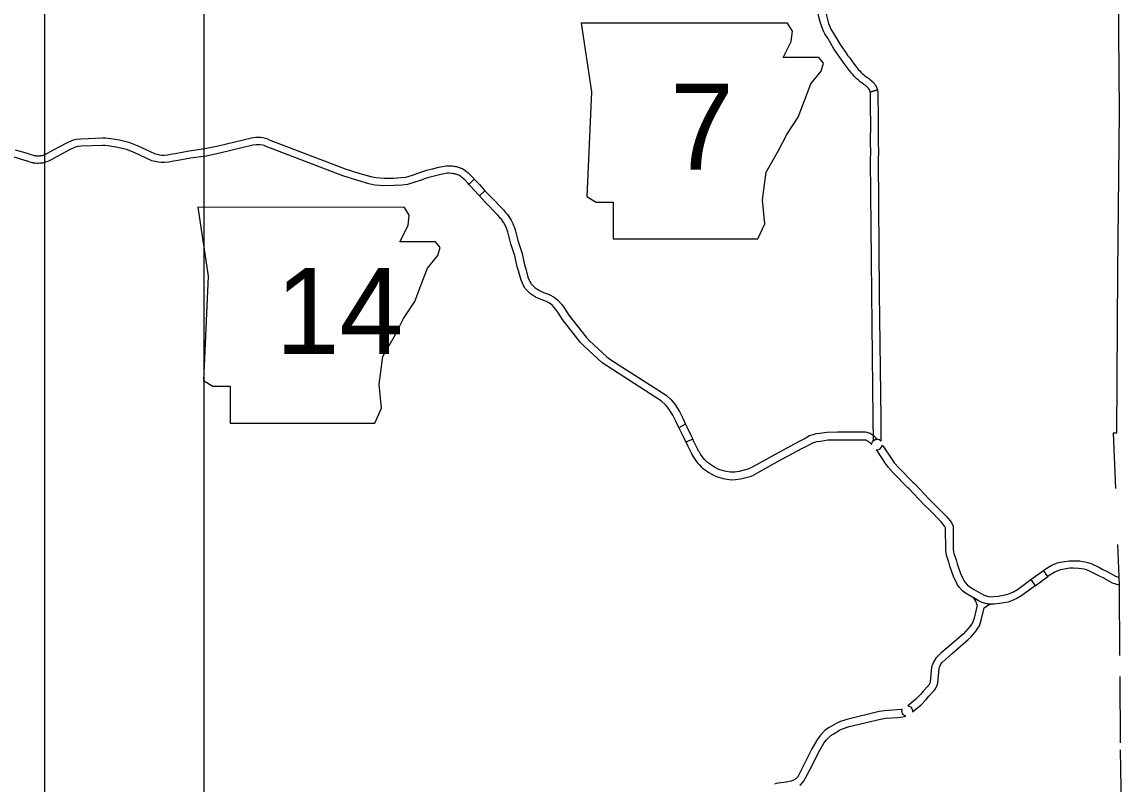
# Model space of a CAD drawing. Extents: x 77230 to 630905, y 790554 to 1662844.
# Drawn here: x 585543 to 621976, y 1603582 to 1628851 of the extents above; entities that cross this region are included whole.
import ezdxf

# ---------------------------------------------------------------- set-up
doc = ezdxf.new("R2010")
doc.units = 0
for name, color, linetype in [('Level 10', 7, 'Continuous'), ('Level 24', 7, 'Continuous'), ('Level 28', 7, 'Continuous'), ('Level 43', 7, 'Continuous')]:
    doc.layers.add(name, color=color, linetype=linetype)

msp = doc.modelspace()

# ---------------------------------------------------------------- linework, layer by layer
at = {"layer": 'Level 10'}
msp.add_line((613598, 1615232), (613558, 1615243), dxfattribs=at)
for points in [[(612461, 1627963), (612252, 1628310), (612161, 1628461), (612128, 1628523), (612090, 1628600), (612047, 1628721), (612001, 1628861), (611963, 1629018), (611939, 1629147), (611842, 1629677), (611783, 1629956), (611720, 1630342), (611665, 1630570), (611633, 1630696), (611560, 1630975), (611541, 1631046), (611530, 1631097), (611518, 1631152), (611504, 1631237)], [(611753, 1631262), (611764, 1631199), (611775, 1631148), (611784, 1631104), (611801, 1631040), (611875, 1630759), (611908, 1630630), (611965, 1630391), (612029, 1630003), (612088, 1629725), (612185, 1629192), (612208, 1629070), (612242, 1628929), (612283, 1628802), (612321, 1628697), (612350, 1628637), (612378, 1628585), (612466, 1628439), (612668, 1628104)], [(613903, 1626598), (613663, 1626529), (613657, 1626551), (613653, 1626564), (613650, 1626571), (613648, 1626577), (613644, 1626585), (613641, 1626593), (613637, 1626601), (613633, 1626608), (613631, 1626612), (613627, 1626619), (613625, 1626622), (613621, 1626628), (613615, 1626636), (613612, 1626642), (613606, 1626648), (613601, 1626654), (613584, 1626673), (613572, 1626685), (613562, 1626696), (613533, 1626721), (613511, 1626739), (613489, 1626757), (613454, 1626782), (613391, 1626827), (613333, 1626872), (613274, 1626919), (613231, 1626957), (613190, 1626995), (613130, 1627056), (613080, 1627111), (613043, 1627154), (612970, 1627246), (612929, 1627303), (612768, 1627521), (612719, 1627589), (612610, 1627745), (612461, 1627963)], [(612668, 1628104), (612815, 1627887), (612923, 1627734), (612970, 1627668), (613131, 1627450), (613169, 1627397), (613235, 1627314), (613267, 1627277), (613312, 1627228), (613365, 1627174), (613398, 1627143), (613435, 1627111), (613488, 1627068), (613539, 1627028), (613600, 1626985), (613640, 1626956), (613668, 1626934), (613696, 1626911), (613733, 1626878), (613752, 1626860), (613767, 1626843), (613789, 1626819), (613798, 1626808), (613809, 1626795), (613819, 1626781), (613827, 1626770), (613835, 1626759), (613842, 1626746), (613849, 1626735), (613855, 1626723), (613861, 1626712), (613867, 1626700), (613873, 1626686), (613879, 1626672), (613885, 1626657), (613890, 1626642), (613896, 1626623), (613903, 1626598)], [(613713, 1619856), (613676, 1624278), (613683, 1624550), (613673, 1624835), (613678, 1625531), (613675, 1625946), (613667, 1626209), (613666, 1626484), (613663, 1626529), (613903, 1626598)], [(613903, 1626598), (613916, 1626499), (613917, 1626213), (613925, 1625951), (613928, 1625531), (613923, 1624839), (613933, 1624551), (613926, 1624276), (613963, 1619859)], [(587003, 1624832), (587214, 1624932), (587291, 1624956), (587348, 1624970), (587489, 1624978), (588217, 1625009)], [(588217, 1625009), (588312, 1625005), (588485, 1624985), (588771, 1624938), (589084, 1624867), (589362, 1624758), (589934, 1624487), (590115, 1624445), (590168, 1624440), (590261, 1624439), (590371, 1624450), (590527, 1624480), (590621, 1624492), (591087, 1624581), (591606, 1624654), (592045, 1624742), (593148, 1625012), (593295, 1625034), (593458, 1625028), (593573, 1625009), (593662, 1624987), (593739, 1624946), (596262, 1623982), (596746, 1623830), (597105, 1623726), (597275, 1623692), (597417, 1623679), (597548, 1623671), (597875, 1623674), (598115, 1623691), (598267, 1623710)], [(587122, 1624612), (586712, 1624390), (586506, 1624280), (586424, 1624241), (586364, 1624213), (586328, 1624199), (586290, 1624187), (586254, 1624178), (586218, 1624172), (586184, 1624168), (586131, 1624165), (586079, 1624164), (586044, 1624164), (585996, 1624167), (585972, 1624169), (585951, 1624171), (585927, 1624174), (585901, 1624180), (585876, 1624185), (585851, 1624192), (585765, 1624219), (585693, 1624243), (585642, 1624259), (585247, 1624377)], [(585319, 1624617), (585715, 1624498), (585770, 1624480), (585842, 1624457), (585922, 1624432), (585937, 1624428), (585951, 1624424), (585967, 1624421), (585982, 1624419), (585999, 1624417), (586014, 1624416), (586051, 1624414), (586076, 1624414), (586122, 1624415), (586162, 1624417), (586181, 1624419), (586203, 1624423), (586220, 1624427), (586243, 1624435), (586266, 1624444), (586319, 1624468), (586394, 1624503), (586593, 1624610), (587003, 1624832)], [(588217, 1624759), (587502, 1624728), (587384, 1624721), (587357, 1624715), (587306, 1624699), (587122, 1624612)], [(598319, 1623464), (598139, 1623442), (597885, 1623425), (597542, 1623421), (597398, 1623430), (597239, 1623444), (597046, 1623483), (596674, 1623590), (596180, 1623746), (593635, 1624718), (593571, 1624752), (593523, 1624764), (593433, 1624779), (593309, 1624783), (593196, 1624766), (592099, 1624498), (591648, 1624407), (591128, 1624334), (590659, 1624244), (590565, 1624233), (590408, 1624203), (590273, 1624188), (590154, 1624190), (590074, 1624198), (589852, 1624249), (589262, 1624528), (589010, 1624628), (588724, 1624693), (588451, 1624737), (588292, 1624755), (588217, 1624759)], [(598267, 1623710), (598487, 1623777), (598697, 1623846), (598836, 1623894), (598966, 1623936), (599153, 1623982), (599366, 1624033), (599533, 1624071), (599621, 1624083), (599703, 1624083), (599806, 1624076), (599845, 1624073), (599885, 1624067), (599910, 1624064), (599942, 1624058), (599976, 1624049), (600006, 1624042), (600040, 1624030), (600073, 1624018), (600133, 1623990), (600185, 1623962), (600235, 1623928), (600276, 1623896), (600331, 1623850), (600394, 1623789), (600517, 1623662), (600538, 1623639), (600357, 1623467)], [(600357, 1623467), (600336, 1623490), (600218, 1623612), (600164, 1623664), (600118, 1623702), (600087, 1623726), (600055, 1623748), (600021, 1623767), (599977, 1623787), (599958, 1623794), (599934, 1623802), (599915, 1623807), (599889, 1623813), (599870, 1623817), (599851, 1623820), (599818, 1623824), (599787, 1623827), (599695, 1623833), (599638, 1623833), (599578, 1623824), (599423, 1623790), (599212, 1623739), (599034, 1623695), (598915, 1623657), (598777, 1623610), (598563, 1623539), (598319, 1623464)], [(600357, 1623467), (600437, 1623380), (600521, 1623288), (600710, 1623082)], [(600538, 1623639), (600621, 1623549), (600705, 1623457), (600891, 1623254)], [(601322, 1622445), (600901, 1622875), (600710, 1623082), (600891, 1623254)], [(600891, 1623254), (601082, 1623048), (601501, 1622620)], [(602087, 1620293), (601999, 1620596), (601961, 1620737), (601877, 1621108), (601870, 1621130), (601861, 1621163), (601762, 1621464), (601750, 1621499), (601740, 1621539), (601648, 1621888), (601628, 1621950), (601606, 1622012), (601582, 1622070), (601559, 1622118), (601540, 1622151), (601524, 1622180), (601506, 1622207), (601471, 1622260), (601435, 1622309), (601411, 1622339), (601383, 1622371), (601322, 1622445)], [(601501, 1622620), (601575, 1622532), (601603, 1622499), (601633, 1622462), (601677, 1622402), (601714, 1622344), (601736, 1622311), (601757, 1622275), (601781, 1622233), (601810, 1622172), (601839, 1622103), (601865, 1622031), (601888, 1621958), (601982, 1621602), (601990, 1621571), (601999, 1621543), (602099, 1621237), (602110, 1621202), (602119, 1621172), (602203, 1620798), (602240, 1620663), (602316, 1620392)], [(607155, 1615752), (607122, 1615809), (606978, 1616032), (606878, 1616152), (606748, 1616274), (604927, 1617444), (604777, 1617549), (604169, 1618113), (604052, 1618238), (603465, 1618982), (603309, 1619230), (603244, 1619321), (603128, 1619446), (603073, 1619494), (603029, 1619526), (602926, 1619585), (602874, 1619609), (602749, 1619651), (602646, 1619693), (602571, 1619729), (602404, 1619841), (602298, 1619935), (602227, 1620015), (602199, 1620055), (602166, 1620112), (602087, 1620293)], [(602316, 1620392), (602389, 1620225), (602409, 1620190), (602423, 1620170), (602475, 1620113), (602557, 1620040), (602696, 1619947), (602748, 1619921), (602836, 1619886), (602967, 1619841), (603040, 1619807), (603164, 1619737), (603229, 1619690), (603303, 1619625), (603438, 1619480), (603517, 1619369), (603670, 1619126), (604241, 1618401), (604346, 1618290), (604935, 1617744), (605067, 1617652), (606902, 1616472), (607060, 1616324), (607180, 1616181), (607335, 1615940), (607378, 1615866)], [(613765, 1614967), (613759, 1615701), (613713, 1619856)], [(613963, 1619859), (614009, 1615704), (614015, 1614954)], [(607378, 1615866), (607445, 1615718), (607542, 1615510)], [(607542, 1615510), (607320, 1615396), (607307, 1615424), (607218, 1615613), (607155, 1615752)], [(607542, 1615510), (607578, 1615431), (607707, 1615173), (607780, 1615016)], [(607320, 1615396), (607353, 1615324), (607482, 1615065), (607549, 1614920)], [(613558, 1615243), (613508, 1615248), (612588, 1615251), (612239, 1615243), (611977, 1615201), (611856, 1615190), (611787, 1615175), (611654, 1615129), (611501, 1615044), (611283, 1614933), (610508, 1614514), (609888, 1614161), (609659, 1614045), (609604, 1614022), (609317, 1613947), (609179, 1613927), (609066, 1613924), (609018, 1613926), (608841, 1613959), (608678, 1614004), (608602, 1614037)], [(613895, 1615013), (613863, 1615049), (613788, 1615116), (613664, 1615202), (613598, 1615232)], [(608602, 1614037), (608505, 1614089), (608444, 1614125), (608374, 1614171), (608321, 1614207), (608270, 1614247), (608248, 1614268), (608181, 1614337), (608127, 1614398), (608087, 1614445), (608033, 1614522), (607997, 1614581), (607973, 1614624), (607944, 1614677), (607836, 1614898), (607793, 1614988), (607780, 1615016), (607549, 1614920)], [(607549, 1614920), (607567, 1614881), (607611, 1614789), (607722, 1614563), (607753, 1614505), (607781, 1614454), (607825, 1614384), (607889, 1614293), (607937, 1614235), (607998, 1614167), (608073, 1614089), (608107, 1614058), (608172, 1614007), (608234, 1613963), (608313, 1613912), (608384, 1613870), (608484, 1613817)], [(608484, 1613817), (608594, 1613768), (608784, 1613715), (608989, 1613677), (609064, 1613674), (609201, 1613678), (609366, 1613702), (609685, 1613784), (609765, 1613818), (610006, 1613941), (610630, 1614296), (611399, 1614711), (611619, 1614823), (611757, 1614900), (611854, 1614933), (611895, 1614942), (612009, 1614953), (612262, 1614993), (612591, 1615001), (613508, 1614998)], [(613508, 1614998), (613539, 1614984), (613633, 1614919), (613685, 1614872), (613709, 1614846)], [(613709, 1614846), (613711, 1614865), (613716, 1614889), (613738, 1614934), (613762, 1614964), (613794, 1614989), (613831, 1615005), (613861, 1615011), (613895, 1615013)], [(614015, 1614954), (613995, 1614973), (613968, 1614992), (613925, 1615008), (613890, 1615013), (613873, 1615013), (613833, 1615005), (613789, 1614985), (613765, 1614967)], [(613863, 1614664), (613890, 1614663), (613932, 1614670), (613975, 1614688), (614026, 1614736), (614051, 1614785), (614058, 1614821)], [(614058, 1614821), (614102, 1614767), (614373, 1614357), (614461, 1614233), (614616, 1614059), (615073, 1613596), (615126, 1613549), (615609, 1613040), (615838, 1612812), (616199, 1612441), (616340, 1612261), (616409, 1612141), (616414, 1611356), (616432, 1611231), (616507, 1611011), (616542, 1610879), (616658, 1610565), (616779, 1610312), (616811, 1610262), (616885, 1610180), (616934, 1610142), (617082, 1610043), (617312, 1609908), (617434, 1609846), (617536, 1609812), (617601, 1609799), (617656, 1609794), (617750, 1609796), (617905, 1609814), (618174, 1609862), (618254, 1609886), (618412, 1609960), (618548, 1610038), (618982, 1610360), (619129, 1610158)], [(619129, 1610158), (618685, 1609829), (618527, 1609738), (618344, 1609653), (618233, 1609618), (617942, 1609567), (617767, 1609546), (617647, 1609544), (617563, 1609551), (617472, 1609571), (617338, 1609615), (617192, 1609689), (616949, 1609831), (616788, 1609938), (616714, 1609996), (616611, 1610110), (616560, 1610191), (616427, 1610468), (616304, 1610803), (616267, 1610938), (616188, 1611173), (616164, 1611337), (616160, 1612074), (616133, 1612121), (616011, 1612276), (615660, 1612637), (615430, 1612866), (614952, 1613369), (614901, 1613414), (614434, 1613888), (614266, 1614077), (614167, 1614215), (613900, 1614619), (613863, 1614664)], [(619401, 1610666), (619461, 1610708), (619658, 1610828), (619751, 1610875), (619907, 1610926), (620252, 1610986), (620398, 1610988), (620609, 1610981), (620702, 1610961), (620785, 1610955), (620871, 1610933), (620987, 1610890), (621263, 1610757), (621375, 1610694), (621521, 1610626), (621792, 1610476), (621900, 1610444), (621911, 1610180)], [(621911, 1610180), (621695, 1610244), (621407, 1610403), (621260, 1610472), (621147, 1610535), (620890, 1610660), (620797, 1610694), (620745, 1610707), (620665, 1610713), (620578, 1610732), (620396, 1610738), (620275, 1610736), (619967, 1610683), (619848, 1610644), (619780, 1610609), (619598, 1610499), (619546, 1610463), (619401, 1610666)], [(618982, 1610360), (619401, 1610666)], [(619129, 1610158), (619546, 1610463)], [(617650, 1609542), (617472, 1609571), (617338, 1609615), (617238, 1609665), (617072, 1609765), (617149, 1609648), (617202, 1609511)], [(617202, 1609511), (617102, 1609080), (617050, 1608928), (617023, 1608881), (616976, 1608816), (616823, 1608638), (616742, 1608556), (616211, 1608097), (616007, 1607916), (615842, 1607758), (615757, 1607628), (615721, 1607542), (615697, 1607454), (615653, 1606975), (615639, 1606925), (615604, 1606861), (615588, 1606839), (615421, 1606657), (615333, 1606552), (615179, 1606396), (614904, 1606174)], [(615061, 1605980), (615347, 1606210), (615518, 1606384), (615609, 1606492), (615781, 1606680), (615815, 1606726), (615872, 1606830), (615900, 1606929), (615944, 1607410), (615958, 1607460), (615979, 1607510), (616036, 1607598), (616176, 1607732), (616376, 1607909), (616913, 1608373), (617007, 1608468), (617173, 1608661), (617234, 1608746), (617279, 1608825), (617343, 1609011), (617439, 1609424)], [(617439, 1609424), (617579, 1609519), (617650, 1609542)], [(614723, 1606062), (614695, 1606055), (614556, 1606040), (614139, 1606012), (613953, 1605982), (612891, 1605727), (612641, 1605643), (612528, 1605584), (612302, 1605455), (612215, 1605399), (612161, 1605357), (612014, 1605203), (611919, 1605070), (611728, 1604751), (611508, 1604308), (611291, 1603884), (611248, 1603812), (611209, 1603768), (611193, 1603757), (611115, 1603711), (611036, 1603682), (610974, 1603665), (610884, 1603646), (610613, 1603616), (610539, 1603599), (610490, 1603582)], [(614840, 1605832), (614810, 1605844), (614778, 1605863), (614750, 1605892), (614732, 1605919), (614717, 1605960), (614712, 1606000), (614716, 1606038), (614723, 1606062)], [(614904, 1606174), (614941, 1606167), (614993, 1606140), (615040, 1606085), (615053, 1606056), (615061, 1606019), (615061, 1605980)], [(611331, 1603548), (611378, 1603583), (611451, 1603663), (611510, 1603763), (611732, 1604196), (611947, 1604631), (612128, 1604933), (612207, 1605043), (612329, 1605171), (612360, 1605195), (612432, 1605241), (612647, 1605364), (612739, 1605412), (612960, 1605487), (614002, 1605736), (614167, 1605763), (614578, 1605791), (614737, 1605808), (614840, 1605832)]]:
    msp.add_lwpolyline(points, dxfattribs=at)
at = {"layer": 'Level 24'}
for points in [[(604078, 1628816), (604421, 1626532), (604268, 1623068), (604573, 1622878), (605144, 1622878), (605144, 1621660), (609940, 1621660), (610169, 1622155), (610092, 1622954), (610207, 1623868), (610625, 1624591), (610892, 1625124), (611272, 1625695), (611501, 1626304), (611691, 1626799), (612034, 1627217), (612110, 1627484), (611958, 1627674), (610778, 1627674), (611044, 1628207), (611082, 1628550), (610924, 1628813)], [(604078, 1628816), (604421, 1626532), (604268, 1623068), (604573, 1622878), (605144, 1622878), (605144, 1621660), (609940, 1621660), (610169, 1622155), (610092, 1622954), (610207, 1623868), (610625, 1624591), (610892, 1625124), (611272, 1625695), (611501, 1626304), (611691, 1626799), (612034, 1627217), (612110, 1627484), (611958, 1627674), (610778, 1627674), (611044, 1628207), (611082, 1628550), (610924, 1628813)], [(591374, 1622708), (591716, 1620424), (591564, 1616960), (591868, 1616770), (592439, 1616770), (592439, 1615552), (597236, 1615552), (597464, 1616047), (597388, 1616846), (597502, 1617760), (597921, 1618483), (598187, 1619016), (598568, 1619587), (598796, 1620196), (598987, 1620691), (599329, 1621110), (599405, 1621376), (599253, 1621566), (598073, 1621566), (598340, 1622099), (598378, 1622442), (598220, 1622705)], [(591374, 1622708), (591716, 1620424), (591564, 1616960), (591868, 1616770), (592439, 1616770), (592439, 1615552), (597236, 1615552), (597464, 1616047), (597388, 1616846), (597502, 1617760), (597921, 1618483), (598187, 1619016), (598568, 1619587), (598796, 1620196), (598987, 1620691), (599329, 1621110), (599405, 1621376), (599253, 1621566), (598073, 1621566), (598340, 1622099), (598378, 1622442), (598220, 1622705)]]:
    msp.add_lwpolyline(points, close=True, dxfattribs=at)
at = {"layer": 'Level 28'}
for p, q in [((591576, 1662844), (591576, 1483324)), ((586296, 1488604), (586296, 1658884))]:
    msp.add_line(p, q, dxfattribs=at)
at = {"layer": 'Level 43'}
for points in [[(621870, 1631143), (621913, 1625874), (621862, 1620576)], [(621862, 1620576), (621824, 1615216), (621719, 1615213), (621789, 1613383)], [(621859, 1611524), (621900, 1610462)], [(621911, 1610172), (621911, 1610164), (621927, 1607845)], [(621932, 1607149), (621947, 1604953)], [(621950, 1604713), (621976, 1602794)]]:
    msp.add_lwpolyline(points, dxfattribs=at)

# ---------------------------------------------------------------- texts
at = {"layer": 'Level 24'}
for s, height, p in [('7', 2851, (607024, 1623951)), ('7', 2851, (607024, 1623951)), ('14', 2851.2, (593948, 1617844)), ('14', 2851.2, (593948, 1617844))]:
    msp.add_text(s, height=height, dxfattribs=at).set_placement(p)

doc.saveas('drawing.dxf')
